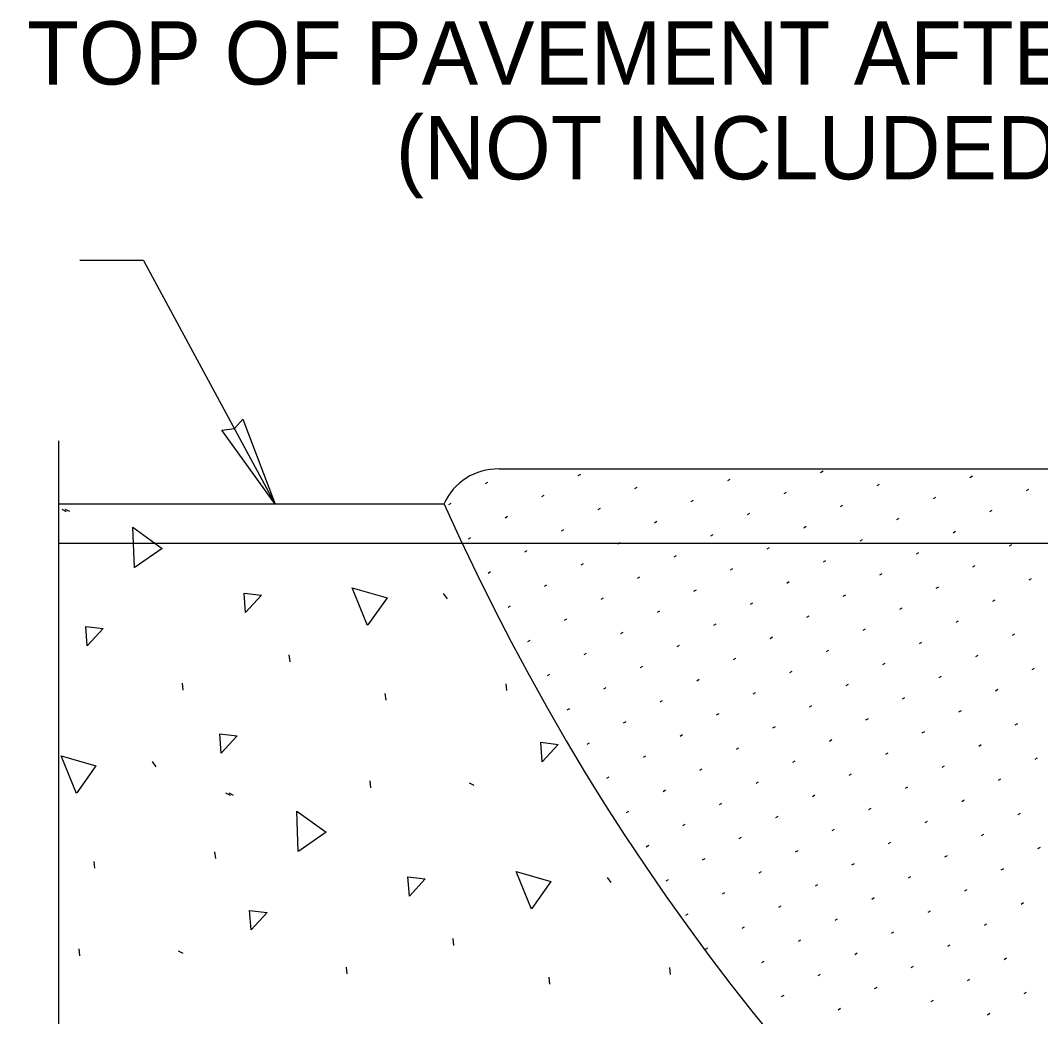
# Model space of a CAD drawing. Extents: x 99862 to 104211, y 98939 to 105076.
# Drawn here: x 100159.9 to 100418.2, y 104124.9 to 104377.1 of the extents above; entities that cross this region are included whole.
import ezdxf

# ---------------------------------------------------------------- set-up
doc = ezdxf.new("R2010")
doc.units = 0
for name, color, linetype in [('Level 1', 7, 'Continuous'), ('Level 15', 7, 'Continuous'), ('Level 20', 7, 'Continuous'), ('Level 3', 7, 'Continuous'), ('Level 4', 7, 'Continuous'), ('Level 6', 7, 'Continuous')]:
    doc.layers.add(name, color=color, linetype=linetype)

msp = doc.modelspace()

# ---------------------------------------------------------------- linework, layer by layer
at = {"layer": 'Level 1'}
for p, q in [((100281.11, 104263.53), (100680.82, 104263.53)), ((100267.17, 104254.65), (100169.63, 104254.65))]:
    msp.add_line(p, q, dxfattribs=at)
msp.add_lwpolyline([(100169.63, 104270.65), (100169.63, 104046.2), (100186.33, 104046.2), (100152.93, 104012.79), (100169.63, 104012.79), (100169.63, 103788.62)], dxfattribs=at)
msp.add_arc((100280.81, 104248.62), 14.92, 88.8654, 156.1576, dxfattribs=at)
msp.add_ellipse((100698.76, 104535.63), major_axis=(0, -590.4), ratio=0.83118, start_param=5.208402, end_param=6.283185, dxfattribs=at)
msp.add_ellipse((100698.76, 104535.63), major_axis=(0, -590.4), ratio=0.83118, start_param=5.208402, end_param=6.283185, dxfattribs=at)
at = {"layer": 'Level 15'}
for q in [(100174.95, 104316.29), (100224.46, 104254.65)]:
    msp.add_line((100191.12, 104316.29), q, dxfattribs=at)
msp.add_lwpolyline([(100224.46, 104254.65), (100210.97, 104273.31), (100214.1, 104273.8), (100216.22, 104276.15)], close=True, dxfattribs=at)
at = {"layer": 'Level 3'}
for p, q in [((100301.17, 104261.9), (100301.78, 104262.25)), ((100362.51, 104262.67), (100363.12, 104263.02)), ((100400.31, 104261.4), (100400.92, 104261.75)), ((100277.64, 104259.85), (100278.24, 104260.2)), ((100315.44, 104258.59), (100316.05, 104258.94)), ((100338.98, 104260.63), (100339.58, 104260.98)), ((100376.78, 104259.36), (100377.39, 104259.71)), ((100291.91, 104256.54), (100292.51, 104256.89)), ((100353.24, 104257.32), (100353.85, 104257.67)), ((100391.05, 104256.05), (100391.65, 104256.4)), ((100414.58, 104258.09), (100415.19, 104258.44)), ((100268.37, 104254.5), (100268.98, 104254.85)), ((100329.71, 104255.28), (100330.31, 104255.63)), ((100367.51, 104254.01), (100368.12, 104254.36)), ((100282.64, 104251.19), (100283.24, 104251.54)), ((100306.17, 104253.24), (100306.78, 104253.59)), ((100343.98, 104251.97), (100344.58, 104252.32)), ((100381.78, 104250.7), (100382.39, 104251.05)), ((100405.31, 104252.74), (100405.92, 104253.09)), ((100320.44, 104249.93), (100321.05, 104250.28)), ((100358.24, 104248.66), (100358.85, 104249.01)), ((100273.37, 104245.84), (100273.98, 104246.19)), ((100296.91, 104247.88), (100297.51, 104248.23)), ((100334.71, 104246.62), (100335.31, 104246.97)), ((100396.05, 104247.39), (100396.65, 104247.74)), ((100311.17, 104244.58), (100311.78, 104244.93)), ((100348.98, 104243.31), (100349.58, 104243.66)), ((100372.51, 104245.35), (100373.12, 104245.7)), ((100410.31, 104244.08), (100410.92, 104244.43)), ((100287.64, 104242.53), (100288.24, 104242.88)), ((100325.44, 104241.27), (100326.05, 104241.62)), ((100386.78, 104242.04), (100387.39, 104242.39)), ((100301.91, 104239.22), (100302.51, 104239.57)), ((100339.71, 104237.96), (100340.31, 104238.31)), ((100363.24, 104240), (100363.85, 104240.35)), ((100401.05, 104238.73), (100401.65, 104239.08)), ((100278.37, 104237.18), (100278.98, 104237.53)), ((100316.17, 104235.91), (100316.78, 104236.26)), ((100377.51, 104236.69), (100378.12, 104237.04)), ((100415.31, 104235.42), (100415.92, 104235.77)), ((100292.64, 104233.87), (100293.24, 104234.22)), ((100330.44, 104232.61), (100331.05, 104232.96)), ((100353.98, 104234.65), (100354.58, 104235)), ((100391.78, 104233.38), (100392.39, 104233.73)), ((100306.91, 104230.56), (100307.51, 104230.91)), ((100368.24, 104231.34), (100368.85, 104231.69)), ((100406.05, 104230.07), (100406.65, 104230.42)), ((100283.37, 104228.52), (100283.98, 104228.87)), ((100344.71, 104229.3), (100345.31, 104229.65)), ((100382.51, 104228.03), (100383.12, 104228.38)), ((100297.64, 104225.21), (100298.24, 104225.56)), ((100321.17, 104227.25), (100321.78, 104227.6)), ((100358.98, 104225.99), (100359.58, 104226.34)), ((100335.44, 104223.95), (100336.05, 104224.3)), ((100373.24, 104222.68), (100373.85, 104223.03)), ((100396.78, 104224.72), (100397.39, 104225.07)), ((100288.37, 104219.86), (100288.98, 104220.21)), ((100311.91, 104221.9), (100312.51, 104222.25)), ((100349.71, 104220.64), (100350.31, 104220.99)), ((100411.05, 104221.41), (100411.65, 104221.76)), ((100326.17, 104218.59), (100326.78, 104218.94)), ((100363.98, 104217.33), (100364.58, 104217.68)), ((100387.51, 104219.37), (100388.12, 104219.72)), ((100302.64, 104216.55), (100303.24, 104216.9)), ((100340.44, 104215.28), (100341.05, 104215.63)), ((100401.78, 104216.06), (100402.39, 104216.41)), ((100316.91, 104213.24), (100317.51, 104213.59)), ((100354.71, 104211.98), (100355.31, 104212.33)), ((100378.24, 104214.02), (100378.85, 104214.37)), ((100416.05, 104212.75), (100416.65, 104213.1)), ((100293.37, 104211.2), (100293.98, 104211.55)), ((100331.17, 104209.93), (100331.78, 104210.28)), ((100392.51, 104210.71), (100393.12, 104211.06)), ((100307.64, 104207.89), (100308.24, 104208.24)), ((100368.98, 104208.67), (100369.58, 104209.02)), ((100406.78, 104207.4), (100407.39, 104207.75)), ((100321.91, 104204.58), (100322.51, 104204.93)), ((100345.44, 104206.62), (100346.05, 104206.97)), ((100383.24, 104205.36), (100383.85, 104205.71)), ((100298.37, 104202.54), (100298.98, 104202.89)), ((100359.71, 104203.31), (100360.31, 104203.66)), ((100397.51, 104202.05), (100398.12, 104202.4)), ((100312.64, 104199.23), (100313.24, 104199.58)), ((100336.17, 104201.27), (100336.78, 104201.62)), ((100373.98, 104200.01), (100374.58, 104200.36)), ((100350.44, 104197.96), (100351.05, 104198.31)), ((100388.24, 104196.7), (100388.85, 104197.05)), ((100411.78, 104198.74), (100412.39, 104199.09)), ((100303.37, 104193.88), (100303.98, 104194.23)), ((100326.91, 104195.92), (100327.51, 104196.27)), ((100364.71, 104194.65), (100365.31, 104195)), ((100341.17, 104192.61), (100341.78, 104192.96)), ((100378.98, 104191.35), (100379.58, 104191.7)), ((100402.51, 104193.39), (100403.12, 104193.74)), ((100317.64, 104190.57), (100318.24, 104190.92)), ((100355.44, 104189.3), (100356.05, 104189.65)), ((100416.78, 104190.08), (100417.39, 104190.43)), ((100331.91, 104187.26), (100332.51, 104187.61)), ((100393.24, 104188.04), (100393.85, 104188.39)), ((100308.37, 104185.22), (100308.98, 104185.57)), ((100346.17, 104183.95), (100346.78, 104184.3)), ((100369.71, 104185.99), (100370.31, 104186.34)), ((100407.51, 104184.73), (100408.12, 104185.08)), ((100322.64, 104181.91), (100323.24, 104182.26)), ((100383.98, 104182.68), (100384.58, 104183.03)), ((100336.91, 104178.6), (100337.51, 104178.95)), ((100360.44, 104180.64), (100361.05, 104180.99)), ((100398.24, 104179.38), (100398.85, 104179.73)), ((100313.37, 104176.56), (100313.98, 104176.91)), ((100374.71, 104177.33), (100375.31, 104177.68)), ((100412.51, 104176.07), (100413.12, 104176.42)), ((100327.64, 104173.25), (100328.24, 104173.6)), ((100351.17, 104175.29), (100351.78, 104175.64)), ((100388.98, 104174.02), (100389.58, 104174.37)), ((100365.44, 104171.98), (100366.05, 104172.33)), ((100403.24, 104170.72), (100403.85, 104171.07)), ((100341.91, 104169.94), (100342.51, 104170.29)), ((100379.71, 104168.67), (100380.31, 104169.02)), ((100318.37, 104167.9), (100318.98, 104168.25)), ((100356.17, 104166.63), (100356.78, 104166.98)), ((100417.51, 104167.41), (100418.12, 104167.76)), ((100332.64, 104164.59), (100333.24, 104164.94)), ((100370.44, 104163.32), (100371.05, 104163.67)), ((100393.98, 104165.36), (100394.58, 104165.71)), ((100346.91, 104161.28), (100347.51, 104161.63)), ((100408.24, 104162.05), (100408.85, 104162.4)), ((100323.37, 104159.24), (100323.98, 104159.59)), ((100361.17, 104157.97), (100361.78, 104158.32)), ((100384.71, 104160.01), (100385.31, 104160.36)), ((100337.64, 104155.93), (100338.24, 104156.28)), ((100398.98, 104156.7), (100399.58, 104157.05)), ((100351.91, 104152.62), (100352.51, 104152.97)), ((100375.44, 104154.66), (100376.05, 104155.01)), ((100413.24, 104153.39), (100413.85, 104153.74)), ((100328.37, 104150.58), (100328.98, 104150.93)), ((100389.71, 104151.35), (100390.31, 104151.7)), ((100366.17, 104149.31), (100366.78, 104149.66)), ((100403.98, 104148.04), (100404.58, 104148.39)), ((100342.64, 104147.27), (100343.24, 104147.62)), ((100380.44, 104146), (100381.05, 104146.35)), ((100356.91, 104143.96), (100357.51, 104144.31)), ((100394.71, 104142.69), (100395.31, 104143.04)), ((100333.37, 104141.92), (100333.98, 104142.27)), ((100371.17, 104140.65), (100371.78, 104141)), ((100347.64, 104138.61), (100348.24, 104138.96)), ((100385.44, 104137.34), (100386.05, 104137.69)), ((100408.98, 104139.38), (100409.58, 104139.73)), ((100361.91, 104135.3), (100362.51, 104135.65)), ((100376.17, 104131.99), (100376.78, 104132.34)), ((100399.71, 104134.03), (100400.31, 104134.38)), ((100352.64, 104129.95), (100353.24, 104130.3)), ((100413.98, 104130.72), (100414.58, 104131.07)), ((100390.44, 104128.68), (100391.05, 104129.03)), ((100366.91, 104126.64), (100367.51, 104126.99)), ((100404.71, 104125.37), (100405.31, 104125.72))]:
    msp.add_line(p, q, dxfattribs=at)
at = {"layer": 'Level 4'}
for p, q in [((100170.4, 104253.37), (100171.55, 104252.8)), ((100171.21, 104253.37), (100172.36, 104252.81)), ((100266.99, 104231.98), (100267.94, 104230.68)), ((100228.19, 104214.73), (100228, 104216.47)), ((100201.17, 104207.53), (100200.98, 104209.27)), ((100283.06, 104207.42), (100282.88, 104209.16)), ((100252.49, 104204.97), (100252.3, 104206.71)), ((100193.31, 104189.44), (100194.26, 104188.14)), ((100248.65, 104182.83), (100248.47, 104184.57)), ((100273.56, 104184.09), (100274.71, 104183.52)), ((100211.88, 104181.52), (100213.03, 104180.95)), ((100212.7, 104181.53), (100213.84, 104180.96)), ((100209.39, 104164.88), (100209.2, 104166.62)), ((100178.81, 104162.43), (100178.62, 104164.17)), ((100308.47, 104160.13), (100309.42, 104158.83)), ((100269.67, 104142.88), (100269.49, 104144.62)), ((100174.97, 104140.3), (100174.79, 104142.04)), ((100199.88, 104141.55), (100201.03, 104140.98)), ((100242.65, 104135.69), (100242.47, 104137.43)), ((100293.97, 104133.12), (100293.78, 104134.86)), ((100324.54, 104135.57), (100324.36, 104137.31))]:
    msp.add_line(p, q, dxfattribs=at)
for points in [[(100188.8, 104238.54), (100188.43, 104248.78), (100195.83, 104243.42), (100188.96, 104238.63)], [(100247.82, 104223.94), (100243.96, 104233.43), (100252.75, 104230.93), (100247.93, 104224.07)], [(100216.93, 104227.2), (100216.55, 104232.11), (100220.96, 104231.58), (100216.93, 104227.2)], [(100176.86, 104218.73), (100176.49, 104223.64), (100180.9, 104223.11), (100176.86, 104218.73)], [(100210.8, 104191.56), (100210.43, 104196.47), (100214.83, 104195.94), (100210.8, 104191.56)], [(100292.02, 104189.42), (100291.65, 104194.33), (100296.05, 104193.79), (100292.02, 104189.42)], [(100174.14, 104181.4), (100170.29, 104190.9), (100179.08, 104188.39), (100174.26, 104181.54)], [(100230.29, 104166.69), (100229.91, 104176.93), (100237.31, 104171.57), (100230.44, 104166.78)], [(100289.3, 104152.09), (100285.44, 104161.59), (100294.24, 104159.08), (100289.41, 104152.23)], [(100258.41, 104155.35), (100258.03, 104160.26), (100262.44, 104159.73), (100258.41, 104155.35)], [(100218.34, 104146.88), (100217.97, 104151.79), (100222.38, 104151.26), (100218.34, 104146.88)]]:
    msp.add_lwpolyline(points, dxfattribs=at)
at = {"layer": 'Level 6'}
msp.add_line((101379.88, 104244.65), (100169.63, 104244.65), dxfattribs=at)

# ---------------------------------------------------------------- texts
at = {"layer": 'Level 20'}
for s, p in [('TOP OF PAVEMENT AFTER GRINDING', (100161.68, 104360.85)), ('(NOT INCLUDED IN BID ITEM)', (100254.97, 104336.85))]:
    msp.add_text(s, height=16, dxfattribs=at).set_placement(p)

doc.saveas('drawing.dxf')
